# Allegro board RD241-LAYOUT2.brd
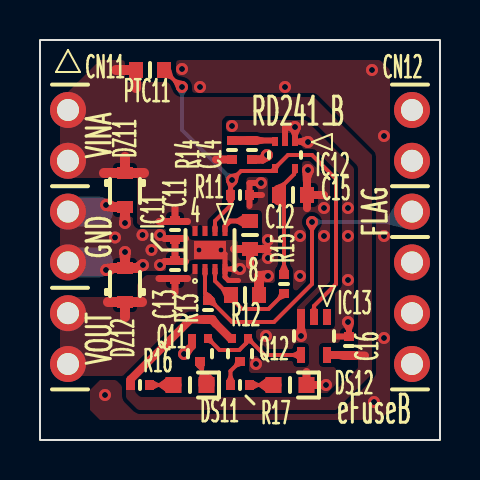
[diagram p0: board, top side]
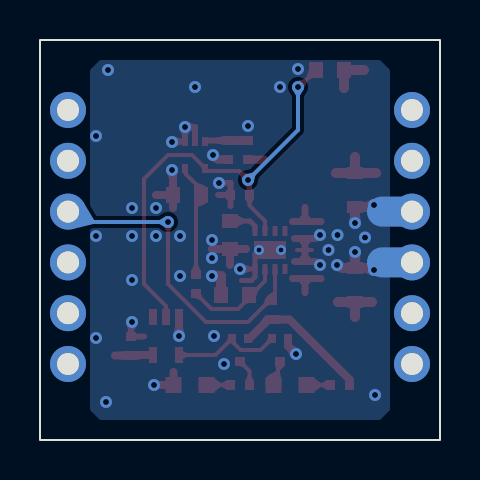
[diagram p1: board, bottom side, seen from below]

Outline 20 x 20 mm; copper layers: TOP, BOTTOM. Coordinates in mm from the lower left corner of the outline.
Outline path: rectangle 0,0 20,20

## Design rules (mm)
constraint set DEFAULT: 

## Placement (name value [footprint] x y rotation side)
C11  -  [CHIP1005_GS_2]  6.75 10.5 270 top
C12  -  [CHIP1608_GS_1]  10.5 10.25 270 top
C13  -  [CHIP1005_GS_2]  6.75 8.5 90 top
C14  -  [CHIP1005_GS_2]  10.6 14.5 270 top
C15  -  [CHIP1608_GS_1]  12.65 12.25 0 top
C16  -  [CHIP1005_GS_2]  15.45 4.7 90 top
CN11  -  [CN_I_TSW_106_07__S_SAMTEC]  1.4 10.15 270 bottom
CN12  -  [CN_I_TSW_106_07__S_SAMTEC]  18.6 10.15 90 bottom
DS11  -  [LD_S_APT1608_KB_1K_3A]  7.5 2.75 180 top
DS12  -  [LD_S_APT1608_KB_1K_3A]  12.5 2.75 180 top
DZ11  -  [DI_S_ESC_TS_1A_3K]  4.25 12.5 90 top
DZ12  -  [DI_S_ESC_TS_1A_3K]  4.25 7.75 270 top
IC11  -  [IC_S_SON_TCKE905NA_TS]  8.5 9.5 180 top
IC12  -  [IC_S_SMD_ESV_TS]  12.25 14.25 180 top
IC13  -  [IC_S_SMD_USV_TS]  13.7 5.2 180 top
PTC11  -  [CHIP1608_GS_1]  5.5 18.5 0 top
Q11  -  [FET_S_VESM_TS_2G_3S_1D]  8 4.5 180 top
Q12  -  [FET_S_VESM_TS_2G_3S_1D]  10 4.5 180 top
R11  -  [CHIP1005_GS_2]  10 12.25 180 top
R12  -  [CHIP1608_GS_1]  10.25 7.25 180 top
R13  -  [CHIP1005_GS_2]  8.4 6.5 270 top
R14  -  [CHIP1005_GS_2]  9.6 14.5 270 top
R15  -  [CHIP1005_GS_2]  12.2 7.8 270 top
R16  -  [CHIP1005_GS_2]  5 2.75 180 top
R17  -  [CHIP1005_GS_2]  10 2.75 180 top

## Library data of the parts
C11 C13 C14 C16 R11 R13-R17 = Chip1005_GS_2
C12 C15 PTC11 R12 = Chip1608_GS_1
CN11 CN12 = TSW-106-07-G-S_SAMTEC
DS11 DS12 = APT1608_KB_1K-3A
DZ11 DZ12 = CEZ6V8_TS_1A-3K
IC11 = TCKE905NA_TS
IC12 = TCTH021BE_TS
IC13 = TC7SH34FU_TS
Q11 = SSM3K35MFV_TS_2G-3S-1D
Q12 = SSM3J35AMFV_TS_2G-3S-1D

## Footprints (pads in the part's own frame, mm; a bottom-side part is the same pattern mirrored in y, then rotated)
CHIP1005_GS_2
  rect 0.45x0.5 smd: 1(-0.475,0) 2(0.475,0)
CHIP1608_GS_1
  rect 0.7x0.8 smd: 1(-0.7,0) 2(0.7,0)
CN_I_TSW_106_07__S_SAMTEC
  round 1.8 hole 1.1: 1(-6.35,0) 2(-3.81,0) 3(-1.27,0) 4(1.27,0) 5(3.81,0) 6(6.35,0)
DI_S_ESC_TS_1A_3K
  rect 0.6x0.8 smd: 1(-0.85,0) 3(0.85,0)
FET_S_VESM_TS_2G_3S_1D
  rect 0.5x0.45 smd: 1(0,0.575)
  rect 0.4x0.45 smd: 2(-0.4,-0.575) 3(0.4,-0.575)
IC_S_SMD_ESV_TS
  rect 0.3x0.45 smd: 1(-0.5,-0.675) 2(0,-0.675) 3(0.5,-0.675) 4(0.5,0.675) 5(-0.5,0.675)
IC_S_SMD_USV_TS
  rect 0.4x0.8 smd: 1(-0.65,-0.95) 2(0,-0.95) 3(0.65,-0.95) 4(0.65,0.95) 5(-0.65,0.95)
IC_S_SON_TCKE905NA_TS
  rect 0.25x0.5 smd: 1(-0.75,-0.95) 2(-0.25,-0.95) 3(0.25,-0.95) 4(0.75,-0.95) 5(0.75,0.95) 6(0.25,0.95) 7(-0.25,0.95) 8(-0.75,0.95)
  rect 1.6x0.9 smd: 9(0,0)
LD_S_APT1608_KB_1K_3A
  rect 0.8x0.8 smd: 1(-0.825,0) 3(0.825,0)

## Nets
GND_B: C11.2 C12.2 C13.2 C14.2 C15.2 C16.2 CN11.3 CN11.4 DS12.1 DZ11.1 DZ12.1 IC11.8 IC11.9 IC12.1 IC12.2 IC13.3 Q11.3 R11.1 R12.1
VINA_B: C11.1 C16.1 CN11.1 CN11.2 DZ11.3 IC11.3 IC11.4 IC13.5 PTC11.1 Q12.3 R13.2 R14.2 R16.2
FLAG_B: CN12.4 IC11.6 R13.1
VOUT_B: C13.1 CN11.5 CN11.6 DZ12.3 IC11.5
N441932: DS11.1 Q11.1
N445247: IC11.2 IC12.4 IC13.2 PTC11.2 R11.2
N445555: IC11.7 R12.2 R15.2
N450530: C14.1 IC12.3 R14.1
N450619: C15.1 IC12.5 R15.1
N451799: DS11.3 R16.1
N475611: DS12.3 R17.1
N478915: C12.1 IC11.1
N478947: IC13.4 Q11.2 Q12.2
N478963: Q12.1 R17.2

Pads without a net: CN12 1 2 3 5 6; IC13 1

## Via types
v1: diameter 0.6, hole 0.3, TOP to BOTTOM, 45 vias
v2: diameter 0.5, hole 0.25, TOP to BOTTOM, 2 vias

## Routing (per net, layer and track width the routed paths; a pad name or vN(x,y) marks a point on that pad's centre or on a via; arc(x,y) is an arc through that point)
GND_B: length 31.7
  TOP w0.2: 6.4,9.5 7.15,9.5
  TOP w0.25: IC11.8 9.25,9.3 v2(9.05,9.5) ; IC11.8 v1(10,8.55) ; IC11.8 9.25,8.15 9.43,7.97 9.93,7.97
  TOP w0.3: IC12.2 12.25,15.65 v1(12.75,15.65) IC12.1 13.01,14.93 v1(13.4,14.9) ; R11.1 11.1,12.25 ; R11.1 10.47,12.85 v1(11.05,12.85) ; R11.1 10.47,11.7 ; v1(15.4,5.9) 15.45,5.51 C16.2 14.8,5.17
  TOP w0.35: 6.75,10.07 6.22,10.07 ; 6.75,10.07 C11.2 C13.2 6.75,8.93 ; 6.75,10.07 7.28,10.07 ; 6.75,8.93 7.28,8.93 ; 6.75,8.93 6.22,8.93
  TOP w0.4: v1(13.4,13.5) 13.35,13.11 C15.2 ; v1(7.2,4.3) 7.6,4.7 Q11.3 ; C12.2 11.4,9.55 ; C12.2 10.5,8.75 ; C12.2 9.7,9.55 ; v1(11.35,14.25) 11.12,14.03 C14.2 ; C15.2 13.35,11.6 ; C15.2 14.2,12.25 ; IC13.3 v1(13.05,5.2) ; v1(14.3,2.75) DS12.1 13.32,3.4
  TOP w0.5: v1(3.3,8.5) 3.68,8.6 DZ12.1 ; v1(5.15,8.75) 4.86,8.6 DZ12.1 ; R12.1 10.95,8.2 v1(11.4,8.2) ; DZ12.1 v1(4.25,9.4) ; v1(3.3,11.75) 3.68,11.65 DZ11.1 v1(4.25,10.85)
  BOTTOM w1.5: CN11.4 2.9,8.88 ; CN11.3 2.9,11.42
  vias: v1(3.25,2.25) v1(3.75,10.12) v1(5.12,10.25) v1(5.58,9.5) v1(6,10.25) v1(6,8.75) v1(7.1,18.55) v1(8,17.65) v1(9.6,15.7) v1(10.8,3.8) v1(11.3,5.2) v1(11.4,10) v1(11.4,9.1) v1(12.25,17.65) v1(13,10.2) v1(13,8.2) v1(14.2,11.6) v1(14.2,10.2) v1(15.4,11.6) v1(15.4,10.2) v1(15.4,8) v1(16.6,18.5) v1(16.7,1.9) v1(17.2,15.2) v1(17.2,10.2) v1(17.2,5.1) v2(7.95,9.5)
VINA_B: length 16.5
  TOP w0.35: 6.75,11.62 C11.1 6.75,10.93 ; 6.75,10.93 7.38,10.93 ; 6.75,10.93 5.95,10.93
  TOP w0.4: 15.24,4.22 14.95,4.25 IC13.5 ; R16.2 4.53,3.02 7.53,6.03 8.26,6.03 ; R14.2 8.8,14.03 ; 15.66,4.22 16.25,4.22 ; Q12.3 9.53,5.08 8.8,5.8 8.61,6.03
  TOP w0.45: 8.26,6.03 R13.2 8.61,6.03 ; 15.24,4.22 15.66,4.22
  TOP w0.5: DZ11.3 3.2,13.35 ; DZ11.3 4.25,14.15 ; DZ11.3 5.2,13.35 ; 4.8,17.6 PTC11.1 3.8,18.5
FLAG_B: length 16.3
  TOP w0.2: 8.4,7.1 8.25,7.35 8.25,8.32 ; v1(13.6,10.9) 13.6,7.8 11.7,5.9 9.6,5.9 8.73,6.77 8.53,6.97
  TOP w0.25: IC11.6 8.25,8.32
  TOP w0.45: 8.53,6.97 R13.1 8.4,7.1
  BOTTOM w0.2: CN12.4 17.35,10.9 v1(13.6,10.9)
VOUT_B: length 4.6
  TOP w0.35: 6.75,8.07 5.95,8.07 ; 6.75,8.07 C13.1 6.75,7.38 ; 6.75,8.07 7.38,8.07
  TOP w0.5: DZ12.3 3.4,6.9 ; DZ12.3 4.25,6.15 ; DZ12.3 5.1,6.9
N441932: length 1.2
  TOP w0.2: 8,3.8 8.1,3.52 8.1,3.39 8.32,2.92
  TOP w0.45: Q11.1 8,3.8
  TOP w0.8: 8.32,2.92 DS11.1
N445247: length 23.4
  TOP w0.2: 11.75,13.6 12.4,14.25 13.6,14.25 14.8,13.05 14.8,7.8 13.7,6.7 13.7,6.35 ; 9.53,12.29 9.53,12.62 v1(9.6,13) 10.05,13.45 11.62,13.45 IC12.4 ; 8.75,10.6 8.75,10.95 9.53,11.72 9.53,12.12 ; PTC11.2 6.76,17.94 v1(7.1,17.65)
  TOP w0.25: IC11.2 8.75,10.6
  TOP w0.3: 11.75,13.6 IC12.4
  TOP w0.4: IC13.2 13.7,6.35
  TOP w0.45: 9.53,12.12 R11.2 9.53,12.29
  BOTTOM w0.2: v1(7.1,17.65) 7.1,15.5 v1(9.6,13)
N445555: length 5
  TOP w0.2: 8.75,8.35 8.75,7.95 9.15,7.55 R12.2 9.79,6.86 10.1,6.55 11.43,6.55 R15.2
  TOP w0.25: IC11.7 8.75,8.35
N450530: length 2.2
  TOP w0.3: IC12.3 11.75,14.97 10.78,14.97
  TOP w0.4: 10.39,14.97 9.72,14.97
  TOP w0.45: 9.72,14.97 R14.1 ; 10.78,14.97 C14.1 10.39,14.97
N450619: length 5.7
  TOP w0.2: 11.95,12.41 12.2,12.79 12.7,13.29 12.7,13.31 12.75,13.5 ; 12.2,8.42 12.2,11.71 11.95,12.09
  TOP w0.3: IC12.5 12.75,13.5
  TOP w0.45: 12.2,8.42 R15.1
  TOP w0.7: 11.95,12.41 C15.1 11.95,12.09
N451799: length 1.2
  TOP w0.2: 6.51,2.75 5.6,2.75
  TOP w0.45: 5.6,2.75 R16.1
  TOP w0.8: DS11.3 6.51,2.75
N475611: length 1.2
  TOP w0.2: 10.6,2.75 11.51,2.75
  TOP w0.45: R17.1 10.6,2.75
  TOP w0.8: 11.51,2.75 DS12.3
N478915: length 1.6
  TOP w0.25: IC11.1 9.25,10.7 9.5,10.95 10.32,10.95
  TOP w0.7: 10.32,10.95 C12.1
N478947: length 5.5
  TOP w0.2: 12.93,4.25 11.22,4.25 Q12.2 10.3,4.83 9.96,4.5 8.97,4.5 Q11.2
  TOP w0.4: 12.93,4.25 IC13.4
N478963: length 1.4
  TOP w0.2: 9.53,2.88 9.53,3.45 Q12.1
  TOP w0.45: 9.53,2.88 R17.2

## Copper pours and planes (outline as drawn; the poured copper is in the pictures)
GND_B on TOP: 13,6 12.89,6.04 12.85,6.15 12.85,6.56 12.86,6.62 13.81,7.59 13.88,7.69 13.9,7.8 13.9,10.4 13.9,10.43 13.91,10.45 14.03,10.65 13.6,11.4 13.17,10.65 13.29,10.45 13.3,10.43 13.3,10.4 13.3,7.97 13.29,7.93 13.27,7.89 12.91,7.53 12.74,7.5 12.65,7.64 12.65,8.47 12.63,8.56 12.58,8.64 12.56,8.66 12.55,8.67 12.51,8.79 12.5,8.83 12.5,11.5 12.54,11.61 12.65,11.65 13.68,11.65 13.83,11.72 13.9,11.88 13.9,12.62 13.83,12.78 13.68,12.85 13.25,12.85 13.14,12.89 13.1,13 13.1,13.8 13.14,13.91 13.25,13.95 13.43,13.95 13.47,13.94 13.51,13.92 14.47,12.96 14.49,12.92 14.5,12.88 14.5,7.97 14.49,7.93 14.47,7.89 13.29,6.72 13.26,6.67 13.25,6.61 13.25,6.15 13.21,6.04 13.1,6
GND_B on TOP: outline of 98 points within 6.75,7.85 11.9,13.15
GND_B on TOP: outline of 102 points within 9.3,2.35 15.7,16
GND_B on TOP: 3.04,1 3,1.01 2.97,1.03 2.53,1.47 2.51,1.5 2.5,1.54 2.5,2.46 2.51,2.5 2.53,2.53 2.97,2.97 3,2.99 3.04,3 3.72,3 3.77,2.99 3.86,2.94 4.04,2.76 4.07,2.72 4.1,2.62 4.1,2.18 4.15,1.98 4.22,1.9 4.7,1.42 4.88,1.31 4.98,1.3 14.74,1.3 14.91,1.35 14.99,1.4 16.7,3.11 16.79,3.27 16.8,3.36 16.8,13.55 16.8,13.57 16.8,14.19 16.75,14.36 16.7,14.44 13.89,17.25 13.73,17.34 13.64,17.35 7.75,17.35 7.64,17.39 7.6,17.5 7.6,17.65 7.5,17.96 7.23,18.13 6.94,18.21 6.91,18.22 6.89,18.23 6.86,18.27 6.84,18.29 6.83,18.31 6.8,18.43 6.8,18.85 6.84,18.96 6.95,19 16.94,19 17.04,18.96 17.46,18.54 17.5,18.44 17.5,1.54 17.49,1.5 17.47,1.47 17.03,1.03 17,1.01 16.96,1
GND_B on BOTTOM: 17.47,1.47 17.03,1.03 16.96,1 3.04,1 2.97,1.03 2.53,1.47 2.5,1.54 2.5,18.44 2.51,18.5 2.54,18.54 2.96,18.96 3,18.99 3.06,19 16.94,19 17,18.99 17.04,18.96 17.46,18.54 17.49,18.5 17.5,18.44 17.5,11.75 17.5,11.73 17.49,11.7 17.21,11.25 17.18,11.21 17.13,11.2 14.1,11.2 14.07,11.2 14.05,11.21 13.73,11.38 13.6,11.4 13.1,10.9 13.6,10.4 13.73,10.42 13.85,10.47 14.05,10.59 14.07,10.6 14.1,10.6 17.31,10.6 17.42,10.57 17.48,10.54 17.5,10.48 17.5,1.54 ; 1 cut-out
VINA_B on TOP: outline of 118 points within 1,1.5 16.6,19
VOUT_B on TOP: 1.2,3.2 1.06,3.26 1,3.4 1,6.95 1.06,7.09 1.2,7.15 3.45,7.15 3.59,7.09 3.65,6.95 3.65,6.62 3.72,6.47 3.88,6.4 4.62,6.4 4.78,6.47 4.85,6.62 4.85,7.74 4.89,7.84 5.26,8.21 5.36,8.25 6.2,8.25 6.27,8.22 6.3,8.15 6.3,7.83 6.37,7.67 6.53,7.6 6.97,7.6 7.13,7.67 7.2,7.83 7.2,8.15 7.23,8.22 7.3,8.25 7.42,8.25 7.57,8.31 7.62,8.45 7.62,8.68 7.75,8.8 7.88,8.68 7.88,6.53 7.85,6.45 7.78,6.42 7.53,6.42 7.37,6.39 7.24,6.31 6.9,5.97 4.18,3.24 4.13,3.21 4.07,3.2

Small or netless copper shapes (teardrops, artwork), in the pictures only: 60 on TOP, 4 on BOTTOM

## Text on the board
Ref Des/Silkscreen Top: CN11 | PTC11 | R16 | Q11 | 4 | R11 | DS11 | R12 | 8 | Q12 | R17 | C12 | IC12 | C15 | DS12 | IC13 | CN12 | DZ12 | DZ11 | IC11 | C13 | C11 | R13 | R14 | C14 | R15 | C16 | VINA | GND | VOUT | FLAG | RD241 B | eFuseB
